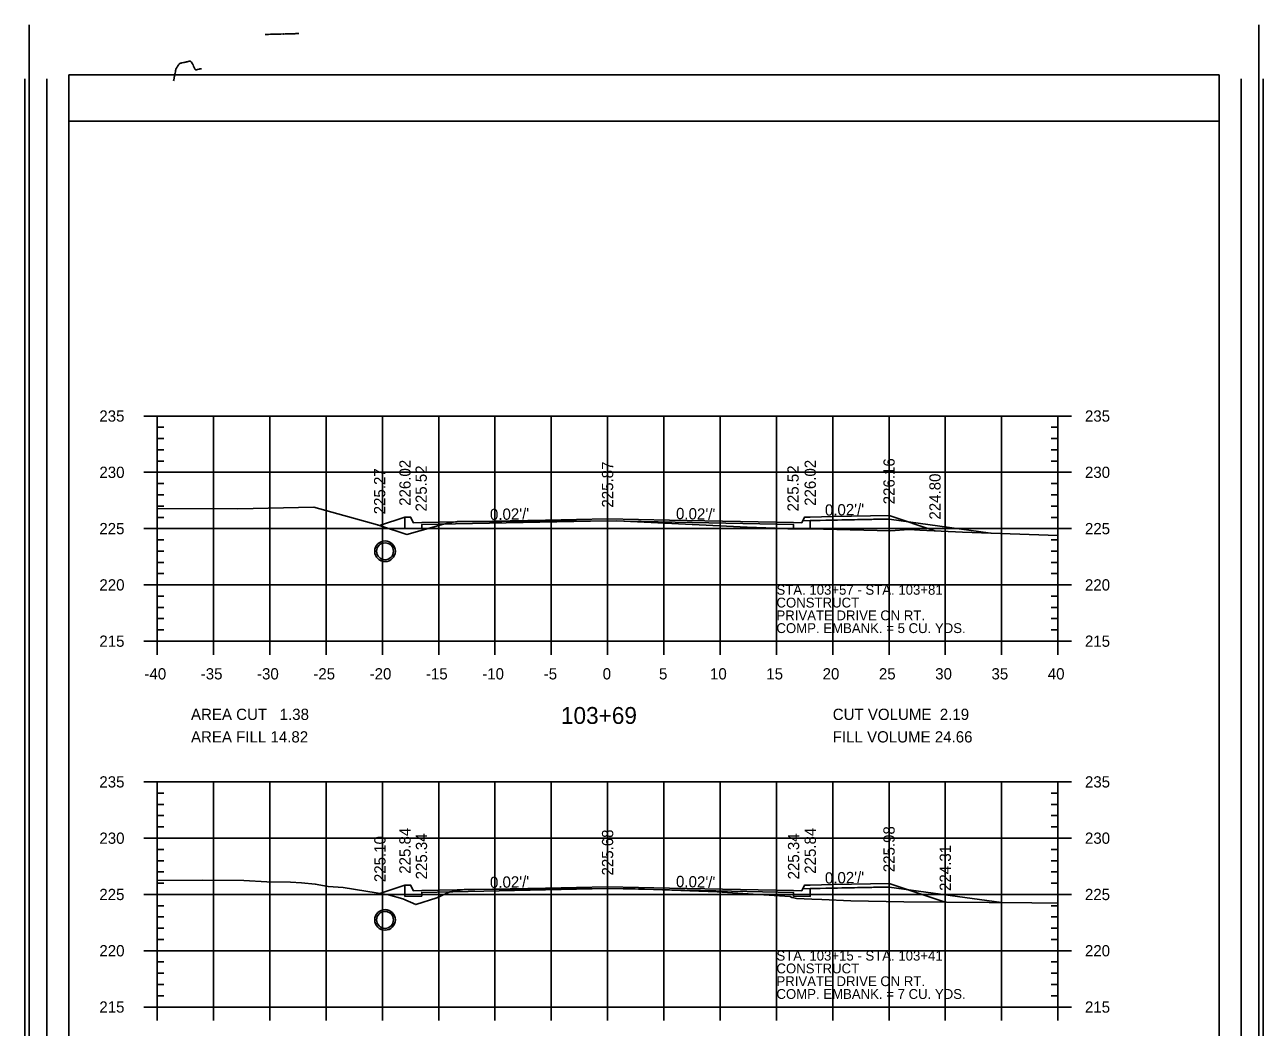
# Model space of a CAD drawing. Extents: x 1367903 to 1373764, y 376865 to 382130.
# Drawn here: x 1370451.5 to 1370671.5, y 377442.3 to 377620.4 of the extents above; entities that cross this region are included whole.
import ezdxf

# ---------------------------------------------------------------- set-up
doc = ezdxf.new("R2010")
doc.units = 0
for name, color, linetype in [('R_Axis', 7, 'Continuous'), ('R_Axis Annot', 7, 'Continuous'), ('R_Border', 7, 'Continuous'), ('R_Border PE', 7, 'Continuous'), ('R_Draft', 7, 'Continuous'), ('R_Drive', 7, 'Continuous'), ('R_Exist Surface', 7, 'Continuous'), ('R_Fin Surface', 7, 'Continuous'), ('R_Fin Surface Annot', 7, 'Continuous'), ('R_Grid', 7, 'Continuous'), ('R_Water', 7, 'Continuous')]:
    doc.layers.add(name, color=color, linetype=linetype)

msp = doc.modelspace()

# ---------------------------------------------------------------- linework, layer by layer
for points in [[(1370518.99, 377532.88), (1370518.99, 377532.21), (1370518.99, 377532.21), (1370518.99, 377530.85), (1370521.99, 377530.91), (1370521.99, 377531.57), (1370554.98, 377532.23), (1370587.98, 377531.57), (1370587.98, 377530.91), (1370590.98, 377530.85), (1370590.98, 377532.29), (1370604.98, 377532.57), (1370604.98, 377533.16)], [(1370518.98, 377467.51), (1370518.98, 377466.84), (1370518.98, 377466.84), (1370518.98, 377465.48), (1370521.98, 377465.54), (1370521.98, 377466.21), (1370554.98, 377466.87), (1370587.98, 377466.21), (1370587.98, 377465.54), (1370590.98, 377465.48), (1370590.98, 377466.92), (1370604.98, 377467.2), (1370604.98, 377467.79)]]:
    msp.add_lwpolyline(points)
at = {"layer": 'R_Axis'}
for p, q in [((1370472.58, 377550.84), (1370477.38, 377550.84)), ((1370474.98, 377510.84), (1370474.98, 377550.84)), ((1370637.38, 377550.84), (1370632.58, 377550.84)), ((1370634.98, 377510.84), (1370634.98, 377550.84)), ((1370474.98, 377548.84), (1370476.18, 377548.84)), ((1370634.98, 377548.84), (1370633.78, 377548.84)), ((1370474.98, 377546.84), (1370476.18, 377546.84)), ((1370474.98, 377544.84), (1370476.18, 377544.84)), ((1370634.98, 377546.84), (1370633.78, 377546.84)), ((1370634.98, 377544.84), (1370633.78, 377544.84)), ((1370474.98, 377542.84), (1370476.18, 377542.84)), ((1370634.98, 377542.84), (1370633.78, 377542.84)), ((1370472.58, 377540.84), (1370477.38, 377540.84)), ((1370637.38, 377540.84), (1370632.58, 377540.84)), ((1370474.98, 377538.84), (1370476.18, 377538.84)), ((1370634.98, 377538.84), (1370633.78, 377538.84)), ((1370474.98, 377536.84), (1370476.18, 377536.84)), ((1370634.98, 377536.84), (1370633.78, 377536.84)), ((1370474.98, 377534.84), (1370476.18, 377534.84)), ((1370634.98, 377534.84), (1370633.78, 377534.84)), ((1370474.98, 377532.84), (1370476.18, 377532.84)), ((1370634.98, 377532.84), (1370633.78, 377532.84)), ((1370472.58, 377530.84), (1370477.38, 377530.84)), ((1370637.38, 377530.84), (1370632.58, 377530.84)), ((1370474.98, 377528.84), (1370476.18, 377528.84)), ((1370634.98, 377528.84), (1370633.78, 377528.84)), ((1370474.98, 377526.84), (1370476.18, 377526.84)), ((1370634.98, 377526.84), (1370633.78, 377526.84)), ((1370474.98, 377524.84), (1370476.18, 377524.84)), ((1370474.98, 377522.84), (1370476.18, 377522.84)), ((1370634.98, 377524.84), (1370633.78, 377524.84)), ((1370634.98, 377522.84), (1370633.78, 377522.84)), ((1370472.58, 377520.84), (1370477.38, 377520.84)), ((1370637.38, 377520.84), (1370632.58, 377520.84)), ((1370474.98, 377518.84), (1370476.18, 377518.84)), ((1370634.98, 377518.84), (1370633.78, 377518.84)), ((1370474.98, 377516.84), (1370476.18, 377516.84)), ((1370634.98, 377516.84), (1370633.78, 377516.84)), ((1370474.98, 377514.84), (1370476.18, 377514.84)), ((1370634.98, 377514.84), (1370633.78, 377514.84)), ((1370474.98, 377508.44), (1370474.98, 377513.24)), ((1370474.98, 377512.84), (1370476.18, 377512.84)), ((1370484.98, 377508.44), (1370484.98, 377513.24)), ((1370494.98, 377508.44), (1370494.98, 377513.24)), ((1370504.98, 377508.44), (1370504.98, 377513.24)), ((1370514.98, 377508.44), (1370514.98, 377513.24)), ((1370524.98, 377508.44), (1370524.98, 377513.24)), ((1370534.98, 377508.44), (1370534.98, 377513.24)), ((1370544.98, 377508.44), (1370544.98, 377513.24)), ((1370554.98, 377508.44), (1370554.98, 377513.24)), ((1370564.98, 377508.44), (1370564.98, 377513.24)), ((1370574.98, 377508.44), (1370574.98, 377513.24)), ((1370584.98, 377508.44), (1370584.98, 377513.24)), ((1370594.98, 377508.44), (1370594.98, 377513.24)), ((1370604.98, 377508.44), (1370604.98, 377513.24)), ((1370614.98, 377508.44), (1370614.98, 377513.24)), ((1370624.98, 377508.44), (1370624.98, 377513.24)), ((1370634.98, 377512.84), (1370633.78, 377512.84)), ((1370634.98, 377508.44), (1370634.98, 377513.24)), ((1370472.58, 377510.84), (1370477.38, 377510.84)), ((1370474.98, 377510.84), (1370634.98, 377510.84)), ((1370637.38, 377510.84), (1370632.58, 377510.84)), ((1370472.58, 377485.84), (1370477.38, 377485.84)), ((1370474.98, 377445.84), (1370474.98, 377485.84)), ((1370637.38, 377485.84), (1370632.58, 377485.84)), ((1370634.98, 377445.84), (1370634.98, 377485.84)), ((1370474.98, 377483.84), (1370476.18, 377483.84)), ((1370634.98, 377483.84), (1370633.78, 377483.84)), ((1370474.98, 377481.84), (1370476.18, 377481.84)), ((1370634.98, 377481.84), (1370633.78, 377481.84)), ((1370474.98, 377479.84), (1370476.18, 377479.84)), ((1370634.98, 377479.84), (1370633.78, 377479.84)), ((1370474.98, 377477.84), (1370476.18, 377477.84)), ((1370634.98, 377477.84), (1370633.78, 377477.84)), ((1370472.58, 377475.84), (1370477.38, 377475.84)), ((1370637.38, 377475.84), (1370632.58, 377475.84)), ((1370474.98, 377473.84), (1370476.18, 377473.84)), ((1370634.98, 377473.84), (1370633.78, 377473.84)), ((1370474.98, 377471.84), (1370476.18, 377471.84)), ((1370634.98, 377471.84), (1370633.78, 377471.84)), ((1370474.98, 377469.84), (1370476.18, 377469.84)), ((1370474.98, 377467.84), (1370476.18, 377467.84)), ((1370634.98, 377469.84), (1370633.78, 377469.84)), ((1370634.98, 377467.84), (1370633.78, 377467.84)), ((1370472.58, 377465.84), (1370477.38, 377465.84)), ((1370637.38, 377465.84), (1370632.58, 377465.84)), ((1370474.98, 377463.84), (1370476.18, 377463.84)), ((1370634.98, 377463.84), (1370633.78, 377463.84)), ((1370474.98, 377461.84), (1370476.18, 377461.84)), ((1370634.98, 377461.84), (1370633.78, 377461.84)), ((1370474.98, 377459.84), (1370476.18, 377459.84)), ((1370634.98, 377459.84), (1370633.78, 377459.84)), ((1370474.98, 377457.84), (1370476.18, 377457.84)), ((1370634.98, 377457.84), (1370633.78, 377457.84)), ((1370472.58, 377455.84), (1370477.38, 377455.84)), ((1370637.38, 377455.84), (1370632.58, 377455.84)), ((1370474.98, 377453.84), (1370476.18, 377453.84)), ((1370634.98, 377453.84), (1370633.78, 377453.84)), ((1370474.98, 377451.84), (1370476.18, 377451.84)), ((1370634.98, 377451.84), (1370633.78, 377451.84)), ((1370474.98, 377449.84), (1370476.18, 377449.84)), ((1370474.98, 377443.44), (1370474.98, 377448.24)), ((1370484.98, 377443.44), (1370484.98, 377448.24)), ((1370494.98, 377443.44), (1370494.98, 377448.24)), ((1370504.98, 377443.44), (1370504.98, 377448.24)), ((1370514.98, 377443.44), (1370514.98, 377448.24)), ((1370524.98, 377443.44), (1370524.98, 377448.24)), ((1370534.98, 377443.44), (1370534.98, 377448.24)), ((1370544.98, 377443.44), (1370544.98, 377448.24)), ((1370554.98, 377443.44), (1370554.98, 377448.24)), ((1370564.98, 377443.44), (1370564.98, 377448.24)), ((1370574.98, 377443.44), (1370574.98, 377448.24)), ((1370584.98, 377443.44), (1370584.98, 377448.24)), ((1370594.98, 377443.44), (1370594.98, 377448.24)), ((1370604.98, 377443.44), (1370604.98, 377448.24)), ((1370614.98, 377443.44), (1370614.98, 377448.24)), ((1370624.98, 377443.44), (1370624.98, 377448.24)), ((1370634.98, 377449.84), (1370633.78, 377449.84)), ((1370634.98, 377443.44), (1370634.98, 377448.24)), ((1370472.58, 377445.84), (1370477.38, 377445.84)), ((1370474.98, 377447.84), (1370476.18, 377447.84)), ((1370474.98, 377445.84), (1370634.98, 377445.84)), ((1370637.38, 377445.84), (1370632.58, 377445.84)), ((1370634.98, 377447.84), (1370633.78, 377447.84))]:
    msp.add_line(p, q, dxfattribs=at)
at = {"layer": 'R_Border'}
for p, q in [((1370452.26, 377620.35), (1370452.26, 377279.12)), ((1370670.65, 377620.35), (1370670.65, 377279.12)), ((1370459.29, 377611.47), (1370663.61, 377611.47)), ((1370459.29, 377611.47), (1370459.29, 377280.59)), ((1370663.61, 377280.59), (1370663.61, 377611.47)), ((1370663.61, 377446.03), (1370663.61, 377446.03))]:
    msp.add_line(p, q, dxfattribs=at)
at = {"layer": 'R_Border PE'}
for p, q in [((1370451.45, 377610.76), (1370451.45, 377288.8)), ((1370455.37, 377610.76), (1370455.37, 377288.8)), ((1370667.54, 377288.8), (1370667.54, 377610.76)), ((1370671.45, 377288.8), (1370671.45, 377610.76)), ((1370459.29, 377603.25), (1370663.61, 377603.25)), ((1370459.29, 377288.8), (1370459.29, 377603.25)), ((1370663.61, 377603.25), (1370663.61, 377288.8))]:
    msp.add_line(p, q, dxfattribs=at)
for points in [[(1370496.15, 377618.69), (1370496.09, 377618.69), (1370495.81, 377618.68), (1370495.68, 377618.68), (1370495.61, 377618.67), (1370495.46, 377618.67), (1370495.1, 377618.66), (1370494.77, 377618.65), (1370494.14, 377618.63)], [(1370496.6, 377618.7), (1370496.15, 377618.69)], [(1370500.16, 377618.79), (1370499.81, 377618.78), (1370499.61, 377618.78), (1370499.45, 377618.77), (1370499.23, 377618.76), (1370499.07, 377618.76), (1370498.87, 377618.75), (1370498.63, 377618.75), (1370498.44, 377618.74), (1370498.15, 377618.73), (1370498.06, 377618.73), (1370498, 377618.73), (1370497.79, 377618.72), (1370497.68, 377618.72), (1370497.46, 377618.71), (1370497.38, 377618.72), (1370496.95, 377618.7), (1370496.71, 377618.7), (1370496.6, 377618.7)], [(1370482.84, 377612.54), (1370482.83, 377612.55), (1370482.8, 377612.55), (1370482.78, 377612.55), (1370482.76, 377612.55), (1370482.73, 377612.55), (1370482.71, 377612.55), (1370482.68, 377612.55), (1370482.54, 377612.51), (1370482.42, 377612.48), (1370482.15, 377612.41), (1370481.94, 377612.36), (1370481.91, 377612.35), (1370481.89, 377612.35), (1370481.87, 377612.34), (1370481.86, 377612.34), (1370481.85, 377612.35), (1370481.83, 377612.35), (1370481.8, 377612.36), (1370481.78, 377612.38), (1370481.76, 377612.39), (1370481.74, 377612.4), (1370481.72, 377612.42), (1370481.71, 377612.45), (1370481.69, 377612.47), (1370481.68, 377612.5), (1370481.66, 377612.55), (1370481.56, 377612.76), (1370481.45, 377613), (1370481.34, 377613.23), (1370481.33, 377613.26), (1370481.32, 377613.28), (1370481.28, 377613.34), (1370481.25, 377613.39), (1370481.13, 377613.57), (1370481.05, 377613.69), (1370481.02, 377613.74), (1370481.01, 377613.76), (1370480.99, 377613.78), (1370480.97, 377613.81), (1370480.95, 377613.83), (1370480.94, 377613.84), (1370480.92, 377613.85), (1370480.9, 377613.87), (1370480.89, 377613.87), (1370480.85, 377613.88), (1370480.83, 377613.88), (1370480.81, 377613.88), (1370480.77, 377613.88), (1370480.67, 377613.86), (1370480.5, 377613.82), (1370480.3, 377613.77), (1370480.16, 377613.74), (1370480.05, 377613.72), (1370479.91, 377613.69), (1370479.8, 377613.66), (1370479.62, 377613.63), (1370479.4, 377613.58), (1370479.35, 377613.57), (1370479.23, 377613.54), (1370479.11, 377613.52), (1370479.07, 377613.51), (1370479.04, 377613.5), (1370479.02, 377613.5), (1370479.01, 377613.49), (1370479, 377613.49), (1370478.98, 377613.47), (1370478.95, 377613.46), (1370478.93, 377613.44), (1370478.91, 377613.42), (1370478.88, 377613.39), (1370478.85, 377613.35), (1370478.82, 377613.31), (1370478.79, 377613.26), (1370478.72, 377613.16), (1370478.63, 377613.02), (1370478.55, 377612.89), (1370478.45, 377612.75), (1370478.4, 377612.67), (1370478.37, 377612.62), (1370478.33, 377612.55), (1370478.32, 377612.54), (1370478.31, 377612.52), (1370478.3, 377612.5), (1370478.29, 377612.48), (1370478.29, 377612.46), (1370478.28, 377612.44), (1370478.27, 377612.42), (1370478.27, 377612.39), (1370478.26, 377612.37), (1370478.26, 377612.35), (1370478.26, 377612.33), (1370478.24, 377612.24), (1370478.2, 377612), (1370478.15, 377611.76), (1370478.13, 377611.65), (1370478.05, 377611.18), (1370478.02, 377611.04), (1370477.98, 377610.84), (1370477.93, 377610.54), (1370477.9, 377610.39)]]:
    msp.add_lwpolyline(points, dxfattribs=at)
at = {"layer": 'R_Drive'}
for p, q in [((1370589.65, 377532.21), (1370604.98, 377532.51)), ((1370604.98, 377532.51), (1370622.98, 377530.05)), ((1370589.65, 377466.84), (1370604.98, 377467.15)), ((1370604.98, 377467.15), (1370624.98, 377464.39))]:
    msp.add_line(p, q, dxfattribs=at)
at = {"layer": 'R_Exist Surface'}
for points in [[(1370474.98, 377534.44), (1370489.28, 377534.38), (1370502.78, 377534.65), (1370514.1, 377531.5), (1370514.22, 377531.47), (1370514.26, 377531.45), (1370514.29, 377531.44), (1370514.67, 377531.32), (1370519.34, 377529.82), (1370525.85, 377531.63), (1370526.09, 377531.7), (1370526.38, 377531.75), (1370528.26, 377532.09), (1370536.19, 377532.13), (1370556.63, 377532.22), (1370579.76, 377531.12), (1370586.41, 377530.83), (1370587, 377530.77), (1370593.31, 377530.76), (1370605.22, 377530.46), (1370608.47, 377530.69), (1370610.45, 377530.55), (1370618.02, 377530.23), (1370634.98, 377529.61)], [(1370474.98, 377468.34), (1370483.1, 377468.37), (1370490.35, 377468.31), (1370494.45, 377468.08), (1370498.68, 377468.02), (1370500.62, 377467.9), (1370503.05, 377467.68), (1370505.32, 377467.26), (1370507.99, 377467.07), (1370516.08, 377465.78), (1370518.61, 377465.06), (1370520.91, 377464.04), (1370524.65, 377465.22), (1370526.94, 377466.28), (1370529.55, 377466.74), (1370529.68, 377466.75), (1370530.79, 377466.75), (1370558.28, 377466.89), (1370574.42, 377466.28), (1370580.86, 377465.92), (1370587.41, 377465.45), (1370587.7, 377465.3), (1370587.81, 377465.32), (1370588.56, 377465.14), (1370591.24, 377465.03), (1370593.07, 377464.93), (1370598.21, 377464.72), (1370607.58, 377464.51), (1370630.32, 377464.36), (1370634.98, 377464.29)]]:
    msp.add_lwpolyline(points, dxfattribs=at)
at = {"layer": 'R_Fin Surface'}
for points in [[(1370514.49, 377531.38), (1370518.99, 377532.88), (1370519.99, 377532.88), (1370520.49, 377531.88), (1370521.99, 377531.91), (1370543.98, 377532.35), (1370554.98, 377532.57), (1370565.98, 377532.35), (1370587.98, 377531.91), (1370589.48, 377531.88), (1370589.98, 377532.88), (1370590.98, 377532.88), (1370594.98, 377532.96), (1370604.98, 377533.16), (1370613.14, 377530.44)], [(1370514.54, 377466.03), (1370518.98, 377467.51), (1370519.98, 377467.51), (1370520.48, 377466.51), (1370521.98, 377466.54), (1370543.98, 377466.98), (1370554.98, 377467.2), (1370565.98, 377466.98), (1370587.98, 377466.54), (1370589.48, 377466.51), (1370589.98, 377467.51), (1370590.98, 377467.51), (1370594.98, 377467.59), (1370604.98, 377467.79), (1370614.97, 377464.46)]]:
    msp.add_lwpolyline(points, dxfattribs=at)
at = {"layer": 'R_Grid'}
for p, q in [((1370474.98, 377550.84), (1370634.98, 377550.84)), ((1370474.98, 377510.84), (1370474.98, 377550.84)), ((1370484.98, 377510.84), (1370484.98, 377550.84)), ((1370494.98, 377510.84), (1370494.98, 377550.84)), ((1370504.98, 377510.84), (1370504.98, 377550.84)), ((1370514.98, 377510.84), (1370514.98, 377550.84)), ((1370524.98, 377510.84), (1370524.98, 377550.84)), ((1370534.98, 377510.84), (1370534.98, 377550.84)), ((1370544.98, 377510.84), (1370544.98, 377550.84)), ((1370554.98, 377510.84), (1370554.98, 377550.84)), ((1370564.98, 377510.84), (1370564.98, 377550.84)), ((1370574.98, 377510.84), (1370574.98, 377550.84)), ((1370584.98, 377510.84), (1370584.98, 377550.84)), ((1370594.98, 377510.84), (1370594.98, 377550.84)), ((1370604.98, 377510.84), (1370604.98, 377550.84)), ((1370614.98, 377510.84), (1370614.98, 377550.84)), ((1370624.98, 377510.84), (1370624.98, 377550.84)), ((1370634.98, 377510.84), (1370634.98, 377550.84)), ((1370474.98, 377540.84), (1370634.98, 377540.84)), ((1370474.98, 377530.84), (1370634.98, 377530.84)), ((1370474.98, 377520.84), (1370634.98, 377520.84)), ((1370474.98, 377510.84), (1370634.98, 377510.84)), ((1370474.98, 377485.84), (1370634.98, 377485.84)), ((1370474.98, 377445.84), (1370474.98, 377485.84)), ((1370484.98, 377445.84), (1370484.98, 377485.84)), ((1370494.98, 377445.84), (1370494.98, 377485.84)), ((1370504.98, 377445.84), (1370504.98, 377485.84)), ((1370514.98, 377445.84), (1370514.98, 377485.84)), ((1370524.98, 377445.84), (1370524.98, 377485.84)), ((1370534.98, 377445.84), (1370534.98, 377485.84)), ((1370544.98, 377445.84), (1370544.98, 377485.84)), ((1370554.98, 377445.84), (1370554.98, 377485.84)), ((1370564.98, 377445.84), (1370564.98, 377485.84)), ((1370574.98, 377445.84), (1370574.98, 377485.84)), ((1370584.98, 377445.84), (1370584.98, 377485.84)), ((1370594.98, 377445.84), (1370594.98, 377485.84)), ((1370604.98, 377445.84), (1370604.98, 377485.84)), ((1370614.98, 377445.84), (1370614.98, 377485.84)), ((1370624.98, 377445.84), (1370624.98, 377485.84)), ((1370634.98, 377445.84), (1370634.98, 377485.84)), ((1370474.98, 377475.84), (1370634.98, 377475.84)), ((1370474.98, 377465.84), (1370634.98, 377465.84)), ((1370474.98, 377455.84), (1370634.98, 377455.84)), ((1370474.98, 377445.84), (1370634.98, 377445.84))]:
    msp.add_line(p, q, dxfattribs=at)
at = {"layer": 'R_Water'}
for p, q in [((1370515.46, 377528.66), (1370515.44, 377528.62)), ((1370515.46, 377528.33), (1370515.44, 377528.28)), ((1370515.46, 377525.33), (1370515.44, 377525.28)), ((1370515.46, 377525), (1370515.44, 377524.95)), ((1370515.44, 377463.17), (1370515.45, 377463.13)), ((1370515.44, 377462.84), (1370515.45, 377462.79)), ((1370515.44, 377459.84), (1370515.45, 377459.79)), ((1370515.44, 377459.51), (1370515.45, 377459.46))]:
    msp.add_line(p, q, dxfattribs=at)
for centre, radius in [((1370515.45, 377526.81), 1.83), ((1370515.45, 377526.81), 1.5), ((1370515.45, 377461.32), 1.83), ((1370515.45, 377461.32), 1.5)]:
    msp.add_circle(centre, radius, dxfattribs=at)

# ---------------------------------------------------------------- texts
at = {"layer": 'R_Axis Annot'}
for s, height, p in [('235', 2, (1370464.7, 377549.84)), ('235', 2, (1370639.78, 377549.84)), ('230', 2, (1370464.71, 377539.84)), ('230', 2, (1370639.78, 377539.84)), ('225', 2, (1370464.7, 377529.84)), ('225', 2, (1370639.78, 377529.84)), ('220', 2, (1370464.71, 377519.84)), ('220', 2, (1370639.78, 377519.84)), ('215', 2, (1370464.7, 377509.84)), ('215', 2, (1370639.78, 377509.84)), ('-40', 2, (1370472.71, 377504.04)), ('-35', 2, (1370482.71, 377504.04)), ('-30', 2, (1370492.71, 377504.04)), ('-25', 2, (1370502.71, 377504.04)), ('-20', 2, (1370512.71, 377504.04)), ('-15', 2, (1370522.71, 377504.04)), ('-10', 2, (1370532.71, 377504.04)), ('-5', 2, (1370543.64, 377504.04)), ('0', 2, (1370554.11, 377504.04)), ('5', 2, (1370564.11, 377504.04)), ('10', 2, (1370573.18, 377504.04)), ('15', 2, (1370583.18, 377504.04)), ('20', 2, (1370593.18, 377504.04)), ('25', 2, (1370603.18, 377504.04)), ('30', 2, (1370613.18, 377504.04)), ('35', 2, (1370623.18, 377504.04)), ('40', 2, (1370633.18, 377504.04)), ('AREA CUT   1.38', 2, (1370480.98, 377496.84)), ('103+69', 3, (1370546.7, 377496.14)), ('CUT VOLUME  2.19', 2, (1370594.98, 377496.84)), ('AREA FILL 14.82', 2, (1370480.98, 377492.84)), ('FILL VOLUME 24.66', 2, (1370594.98, 377492.84)), ('235', 2, (1370464.7, 377484.84)), ('235', 2, (1370639.78, 377484.84)), ('230', 2, (1370464.71, 377474.84)), ('230', 2, (1370639.78, 377474.84)), ('225', 2, (1370464.7, 377464.84)), ('225', 2, (1370639.78, 377464.84)), ('220', 2, (1370464.71, 377454.84)), ('220', 2, (1370639.78, 377454.84)), ('215', 2, (1370464.7, 377444.84)), ('215', 2, (1370639.78, 377444.84))]:
    msp.add_text(s, height=height, dxfattribs=at).set_placement(p)
at = {"layer": 'R_Draft'}
for s, p in [('STA. 103+57 - STA. 103+81', (1370584.98, 377519.09)), ('CONSTRUCT', (1370584.98, 377516.82)), ('PRIVATE DRIVE ON RT.', (1370584.98, 377514.55)), ('COMP. EMBANK. = 5 CU. YDS.', (1370584.98, 377512.28)), ('STA. 103+15 - STA. 103+41', (1370584.98, 377454.09)), ('CONSTRUCT', (1370584.98, 377451.82)), ('PRIVATE DRIVE ON RT.', (1370584.98, 377449.55)), ('COMP. EMBANK. = 7 CU. YDS.', (1370584.98, 377447.28))]:
    msp.add_text(s, height=1.75, dxfattribs=at).set_placement(p)
at = {"layer": 'R_Fin Surface Annot'}
for s, rotation, p in [('226.02', 90, (1370519.99, 377534.88)), ('225.87', 90, (1370555.98, 377534.57)), ('226.02', 90, (1370591.98, 377534.88)), ('226.16', 90, (1370605.98, 377535.16)), ('225.27', 90, (1370515.49, 377533.38)), ('225.52', 90, (1370522.87, 377533.88)), ('225.52', 90, (1370588.93, 377533.88)), ('224.80', 90, (1370614.14, 377532.44)), ("0.02'/'", 1.1456, (1370534.11, 377532.35)), ("0.02'/'", 358.854, (1370567.12, 377532.53)), ("0.02'/'", 1.1456, (1370593.61, 377533.13)), ('225.84', 90, (1370519.98, 377469.51)), ('225.34', 90, (1370522.92, 377468.51)), ('225.68', 90, (1370555.98, 377469.2)), ('225.34', 90, (1370589.02, 377468.51)), ('225.84', 90, (1370591.98, 377469.51)), ('225.98', 90, (1370605.98, 377469.79)), ('225.10', 90, (1370515.54, 377468.03)), ('224.31', 90, (1370615.97, 377466.46)), ("0.02'/'", 1.1458, (1370593.61, 377467.76)), ("0.02'/'", 1.1458, (1370534.11, 377466.98)), ("0.02'/'", 358.8542, (1370567.12, 377467.16))]:
    msp.add_text(s, height=2, rotation=rotation, dxfattribs=at).set_placement(p)

doc.saveas('drawing.dxf')
